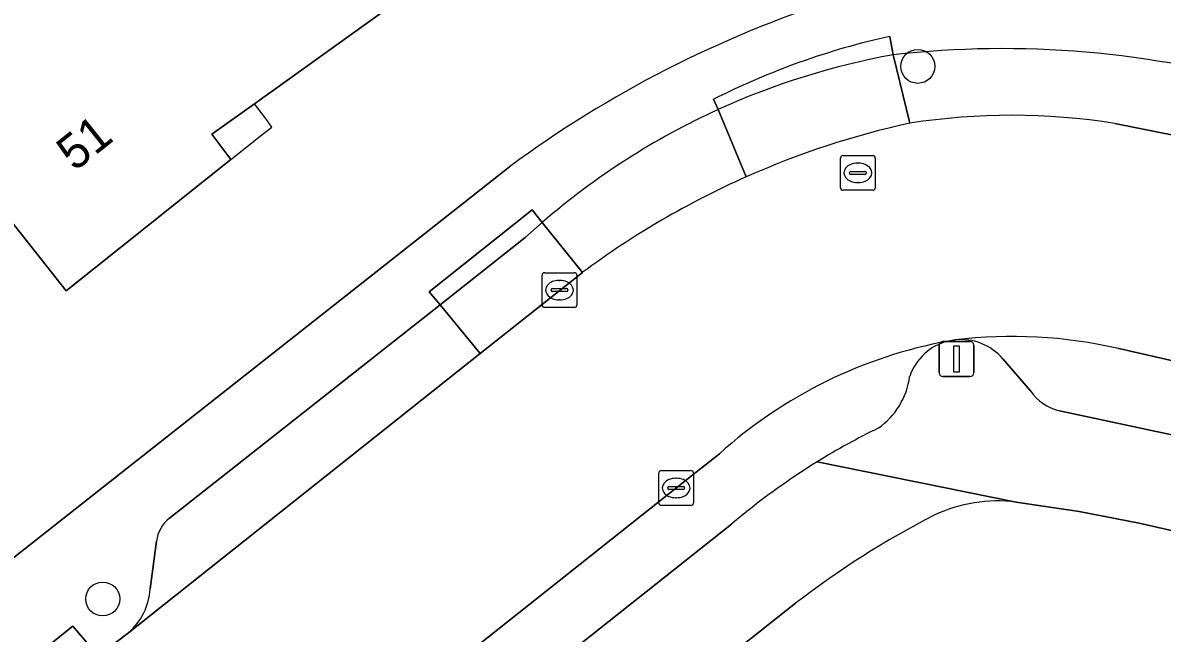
# Model space of a CAD drawing. Extents: x 159626 to 160723, y 388173 to 389416.
# Drawn here: x 160151.28 to 160184.07, y 388726.15 to 388743.72 of the extents above; entities that cross this region are included whole.
import ezdxf

# ---------------------------------------------------------------- set-up
doc = ezdxf.new("R2010")
doc.units = 0
for name, color, linetype in [('IMGEO_Boom', 7, 'Continuous'), ('IMGEO_Erf', 7, 'Continuous'), ('IMGEO_Kolk', 7, 'Continuous'), ('IMGEO_Lichtmast', 7, 'Continuous'), ('IMGEO_Pand', 7, 'Continuous'), ('IMGEO_Pand_nummerreeks', 7, 'Continuous'), ('IMGEO_Pand_overbouw', 7, 'Continuous'), ('IMGEO_Parkeervlak_open', 7, 'Continuous'), ('IMGEO_Rijbaan_lokaal_gesloten', 7, 'Continuous'), ('IMGEO_Rioolput', 7, 'Continuous'), ('IMGEO_Voetpad_open', 7, 'Continuous')]:
    doc.layers.add(name, color=color, linetype=linetype)

msp = doc.modelspace()

# ---------------------------------------------------------------- linework, layer by layer
at = {"layer": 'IMGEO_Boom'}
for centre in [(160177.036, 388742.463), (160153.582, 388727.138)]:
    msp.add_circle(centre, 0.489, dxfattribs=at)
at = {"layer": 'IMGEO_Erf'}
msp.add_lwpolyline([(160150.591, 388750), (160154.519, 388753.109), (160156.98, 388750), (160161.683, 388744.057), (160157.95, 388741.385), (160156.726, 388740.509), (160157.27, 388739.782), (160152.532, 388736.005), (160150.616, 388738.417), (160150.166, 388738.08), (160149.286, 388739.183), (160149.734, 388739.532), (160148.008, 388741.687), (160145.817, 388739.968), (160142.781, 388743.819)], close=True, dxfattribs=at)
for points in [[(160151.026, 388728.336), (160165.29, 388739.573)], [(160223.367, 388703.114), (160224.3, 388707.209), (160227.072, 388719.379), (160183.407, 388729.319), (160181.681, 388729.655), (160179.863, 388729.928)], [(160173.521, 388727.014), (160150.851, 388709.051), (160094.032, 388664.03)]]:
    msp.add_lwpolyline(points, dxfattribs=at)
for centre, radius, start, end in [((160184.6, 388713.456), 32.48, 107.7327, 126.4777), ((160179.343, 388725.64), 4.319, 83.0882, 115.1171), ((160189.291, 388706.623), 25.777, 117.195, 127.7176)]:
    msp.add_arc(centre, radius, start, end, dxfattribs=at)
at = {"layer": 'IMGEO_Kolk'}
for p, q in [((160166.225, 388735.599), (160166.225, 388736.451)), ((160166.3, 388736.525), (160167.152, 388736.525)), ((160167.226, 388736.451), (160167.226, 388735.599)), ((160166.484, 388736.019), (160166.484, 388736.031)), ((160166.527, 388736.068), (160166.925, 388736.068)), ((160166.713, 388736.305), (160166.738, 388736.305)), ((160166.968, 388736.031), (160166.968, 388736.019)), ((160166.922, 388735.982), (160166.524, 388735.982)), ((160166.736, 388735.745), (160166.711, 388735.745)), ((160167.152, 388735.525), (160166.3, 388735.525)), ((160169.582, 388729.905), (160169.582, 388730.757)), ((160169.657, 388730.831), (160170.509, 388730.831)), ((160170.583, 388730.757), (160170.583, 388729.905)), ((160170.07, 388730.611), (160170.095, 388730.611)), ((160169.841, 388730.325), (160169.841, 388730.337)), ((160170.279, 388730.288), (160169.881, 388730.288)), ((160169.884, 388730.374), (160170.282, 388730.374)), ((160170.325, 388730.337), (160170.325, 388730.325)), ((160170.509, 388729.831), (160169.657, 388729.831)), ((160170.093, 388730.051), (160170.068, 388730.051))]:
    msp.add_line(p, q, dxfattribs=at)
for points in [[(160166.225, 388735.599), (160166.225, 388736.451)], [(160166.3, 388736.525), (160167.152, 388736.525)], [(160167.226, 388736.451), (160167.226, 388735.599)], [(160167.152, 388735.525), (160166.3, 388735.525)], [(160169.582, 388729.905), (160169.582, 388730.757)], [(160169.657, 388730.831), (160170.509, 388730.831)], [(160170.583, 388730.757), (160170.583, 388729.905)], [(160170.509, 388729.831), (160169.657, 388729.831)]]:
    msp.add_lwpolyline(points, dxfattribs=at)
for centre, radius, start, end in [((160166.302, 388736.449), 0.0765, 91.552, 178.448), ((160166.302, 388736.449), 0.0765, 91.552, 178.448), ((160167.15, 388736.449), 0.0765, 1.552, 88.448), ((160167.15, 388736.449), 0.0765, 1.552, 88.448), ((160166.524, 388736.028), 0.0403, 85.8775, 175.7526), ((160166.521, 388736.018), 0.0366, 178.938, 274.7102), ((160166.925, 388736.025), 0.043, 264.8664, 352.4533), ((160166.929, 388736.03), 0.0386, 1.7309, 96.639), ((160166.302, 388735.601), 0.0765, 181.552, 268.448), ((160166.302, 388735.601), 0.0765, 181.552, 268.448), ((160167.15, 388735.601), 0.0765, 271.552, 358.448), ((160167.15, 388735.601), 0.0765, 271.552, 358.448), ((160169.659, 388730.755), 0.0765, 91.552, 178.448), ((160169.659, 388730.755), 0.0765, 91.552, 178.448), ((160170.507, 388730.755), 0.0765, 1.552, 88.448), ((160170.507, 388730.755), 0.0765, 1.552, 88.448), ((160169.881, 388730.334), 0.0403, 85.8775, 175.7526), ((160169.878, 388730.324), 0.0366, 178.938, 274.7102), ((160170.282, 388730.331), 0.043, 264.8664, 352.4533), ((160170.286, 388730.336), 0.0386, 1.7309, 96.639), ((160169.659, 388729.907), 0.0765, 181.552, 268.448), ((160169.659, 388729.907), 0.0765, 181.552, 268.448), ((160170.507, 388729.907), 0.0765, 271.552, 358.448), ((160170.507, 388729.907), 0.0765, 271.552, 358.448)]:
    msp.add_arc(centre, radius, start, end, dxfattribs=at)
for centre, major_axis, ratio, start_param, end_param in [((160166.712, 388736.025), (-0.387, 0.002), 0.722429, 4.712389, 7.853982), ((160166.737, 388736.025), (-0.39, 0.002), 0.717154, 1.570796, 4.712389), ((160170.069, 388730.331), (-0.387, 0.002), 0.722429, 4.712389, 7.853982), ((160170.094, 388730.331), (-0.39, 0.002), 0.717154, 1.570796, 4.712389)]:
    msp.add_ellipse(centre, major_axis=major_axis, ratio=ratio, start_param=start_param, end_param=end_param, dxfattribs=at)
at = {"layer": 'IMGEO_Lichtmast'}
for p, q in [((160177.655, 388733.643), (160177.655, 388734.443)), ((160177.655, 388734.443), (160177.655, 388733.643)), ((160177.755, 388734.543), (160178.545, 388734.543)), ((160178.545, 388734.543), (160177.755, 388734.543)), ((160178.645, 388734.443), (160178.645, 388733.643)), ((160178.645, 388733.643), (160178.645, 388734.443)), ((160178.545, 388733.543), (160177.755, 388733.543)), ((160177.755, 388733.543), (160178.545, 388733.543))]:
    msp.add_line(p, q, dxfattribs=at)
msp.add_lwpolyline([(160178.075, 388734.418), (160178.225, 388734.418), (160178.225, 388733.668), (160178.075, 388733.668), (160178.075, 388734.418)], dxfattribs=at)
for centre, start, end in [((160177.755, 388734.443), 90, 180), ((160177.755, 388734.443), 90, 180), ((160178.545, 388734.443), 0, 90), ((160178.545, 388734.443), 360, 90), ((160177.755, 388733.643), 180, 270), ((160177.755, 388733.643), 180, 270), ((160178.545, 388733.643), 270, 0), ((160178.545, 388733.643), 270, 0)]:
    msp.add_arc(centre, 0.1, start, end, dxfattribs=at)
at = {"layer": 'IMGEO_Pand'}
msp.add_lwpolyline([(160157.27, 388739.782), (160156.726, 388740.509), (160157.95, 388741.385), (160161.683, 388744.057), (160156.98, 388750), (160154.519, 388753.109), (160150.591, 388750), (160142.781, 388743.819), (160145.817, 388739.968), (160148.008, 388741.687), (160149.734, 388739.532), (160149.286, 388739.183), (160150.166, 388738.08), (160150.616, 388738.417), (160152.532, 388736.005)], close=True, dxfattribs=at)
at = {"layer": 'IMGEO_Pand_overbouw'}
msp.add_lwpolyline([(160157.27, 388739.782), (160158.208, 388740.528), (160158.446, 388740.716), (160158.268, 388740.968), (160157.95, 388741.385), (160156.726, 388740.509)], close=True, dxfattribs=at)
at = {"layer": 'IMGEO_Parkeervlak_open'}
for points in [[(160176.81, 388740.829), (160176.329, 388742.795)], [(160176.329, 388742.795), (160176.81, 388740.829)], [(160182.708, 388740.822), (160186.699, 388740.022), (160187.729, 388739.79), (160188.156, 388741.666), (160187.322, 388741.856)], [(160171.295, 388741.221), (160172.098, 388739.283)], [(160172.098, 388739.283), (160171.295, 388741.221)], [(160166.231, 388737.973), (160167.383, 388736.528)], [(160164.446, 388734.198), (160163.289, 388735.602), (160155.504, 388729.46)], [(160154.322, 388726.169), (160164.446, 388734.198)], [(160179.479, 388734.048), (160180.281, 388733.126)], [(160186.385, 388733.53), (160182.816, 388734.344)], [(160181.115, 388732.553), (160191.078, 388730.424), (160193.754, 388729.817), (160194.236, 388731.738), (160186.385, 388733.53)], [(160171.328, 388731.319), (160170.527, 388730.683), (160163.509, 388725.123), (160164.631, 388723.707), (160171.673, 388729.291)], [(160155.128, 388728.8), (160154.945, 388727.431)]]:
    msp.add_lwpolyline(points, dxfattribs=at)
msp.add_lwpolyline([(160167.383, 388736.528), (160166.231, 388737.973), (160165.742, 388737.537), (160163.289, 388735.602), (160164.446, 388734.198)], close=True, dxfattribs=at)
for centre, radius, start, end in [((160179.479, 388714.852), 28.12, 73.8041, 96.4315), ((160180.134, 388721.789), 21.348, 100.2671, 114.4591), ((160180.067, 388721.973), 21.152, 114.4999, 130.8515), ((160179.737, 388721.945), 19.109, 81.0545, 98.8095), ((160182.087, 388716.791), 24.611, 102.3822, 113.947), ((160182.134, 388716.694), 24.718, 113.956, 126.64), ((160179.751, 388721.039), 13.653, 77.0286, 96.9177), ((160180.354, 388721.285), 13.496, 100.3895, 131.9731), ((160178.285, 388733.039), 1.564, 103.489, 161.4297), ((160178.282, 388733.034), 1.569, 40.2698, 96.4013), ((160174.667, 388733.822), 2.154, 304.8505, 352.3843), ((160181.439, 388733.919), 1.404, 214.3806, 256.6373), ((160184.873, 388713.738), 20.398, 116.1031, 121.734), ((160185.108, 388713.394), 20.814, 121.7882, 130.2031), ((160156.132, 388728.665), 1.013, 128.301, 172.3589), ((160153.161, 388727.527), 1.786, 310.5258, 356.9267)]:
    msp.add_arc(centre, radius, start, end, dxfattribs=at)
at = {"layer": 'IMGEO_Rijbaan_lokaal_gesloten'}
for points in [[(160187.729, 388739.79), (160186.699, 388740.022), (160182.708, 388740.822)], [(160182.816, 388734.344), (160186.385, 388733.53), (160187.729, 388739.79)], [(160167.383, 388736.528), (160164.446, 388734.198), (160154.322, 388726.169), (160153.45, 388725.499), (160143.876, 388717.854), (160143.646, 388717.671), (160143.177, 388717.325), (160085.885, 388671.953), (160085.177, 388671.383), (160084.775, 388671.059), (160074.107, 388662.597), (160068.619, 388658.215), (160050.132, 388643.587), (160047.169, 388641.243), (160035.367, 388631.905), (160032.398, 388629.556), (160020.566, 388620.194), (160017.62, 388617.863), (160009.366, 388611.332), (160008.998, 388611.041), (160000, 388603.924), (159995.738, 388600.553), (159983.064, 388590.517)], [(160177.92, 388734.56), (160178.107, 388734.593)], [(160076.921, 388656.375), (160090.898, 388667.506), (160104.695, 388678.512), (160114.92, 388686.617), (160117.817, 388688.912), (160122.521, 388692.641), (160125.504, 388695.005), (160129.729, 388698.354), (160132.7, 388700.709), (160137.417, 388704.448), (160140.4, 388706.812), (160145.108, 388710.543), (160148.116, 388712.927), (160152.872, 388716.695), (160155.799, 388719.014), (160160.515, 388722.751), (160163.509, 388725.123), (160170.527, 388730.683), (160171.328, 388731.319)]]:
    msp.add_lwpolyline(points, dxfattribs=at)
for centre, radius, start, end in [((160179.737, 388721.945), 19.109, 81.0545, 98.8095), ((160182.087, 388716.791), 24.611, 102.3822, 113.947), ((160182.134, 388716.694), 24.718, 113.956, 126.64), ((160179.751, 388721.039), 13.653, 77.0286, 96.9177), ((160180.354, 388721.285), 13.496, 100.3895, 131.9731)]:
    msp.add_arc(centre, radius, start, end, dxfattribs=at)
at = {"layer": 'IMGEO_Rioolput'}
for p, q in [((160174.811, 388738.972), (160174.811, 388739.824)), ((160174.886, 388739.898), (160175.738, 388739.898)), ((160175.299, 388739.678), (160175.324, 388739.678)), ((160175.812, 388739.824), (160175.812, 388738.972)), ((160175.07, 388739.392), (160175.07, 388739.404)), ((160175.508, 388739.355), (160175.11, 388739.355)), ((160175.113, 388739.441), (160175.511, 388739.441)), ((160175.554, 388739.404), (160175.554, 388739.392)), ((160175.322, 388739.118), (160175.297, 388739.118)), ((160175.738, 388738.898), (160174.886, 388738.898))]:
    msp.add_line(p, q, dxfattribs=at)
for points in [[(160174.811, 388738.972), (160174.811, 388739.824)], [(160174.886, 388739.898), (160175.738, 388739.898)], [(160175.812, 388739.824), (160175.812, 388738.972)], [(160175.738, 388738.898), (160174.886, 388738.898)]]:
    msp.add_lwpolyline(points, dxfattribs=at)
for centre, radius, start, end in [((160174.888, 388739.822), 0.0765, 91.552, 178.448), ((160174.888, 388739.822), 0.0765, 91.552, 178.448), ((160175.736, 388739.822), 0.0765, 1.552, 88.448), ((160175.736, 388739.822), 0.0765, 1.552, 88.448), ((160175.11, 388739.401), 0.0403, 85.8775, 175.7526), ((160175.107, 388739.391), 0.0366, 178.938, 274.7102), ((160175.511, 388739.398), 0.043, 264.8664, 352.4533), ((160175.515, 388739.403), 0.0386, 1.7309, 96.639), ((160174.888, 388738.974), 0.0765, 181.552, 268.448), ((160174.888, 388738.974), 0.0765, 181.552, 268.448), ((160175.736, 388738.974), 0.0765, 271.552, 358.448), ((160175.736, 388738.974), 0.0765, 271.552, 358.448)]:
    msp.add_arc(centre, radius, start, end, dxfattribs=at)
for centre, major_axis, ratio, start_param, end_param in [((160175.298, 388739.398), (-0.387, 0.002), 0.722429, 4.712389, 7.853982), ((160175.323, 388739.398), (-0.39, 0.002), 0.717154, 1.570796, 4.712389)]:
    msp.add_ellipse(centre, major_axis=major_axis, ratio=ratio, start_param=start_param, end_param=end_param, dxfattribs=at)
at = {"layer": 'IMGEO_Voetpad_open'}
for points in [[(160176.329, 388742.795), (160176.227, 388743.325)], [(160176.227, 388743.325), (160176.329, 388742.795)], [(160171.161, 388741.517), (160171.295, 388741.221)], [(160171.295, 388741.221), (160171.161, 388741.517)], [(160165.29, 388739.573), (160151.026, 388728.336), (160148.356, 388726.193), (160144.483, 388723.108), (160141.674, 388720.846), (160141.623, 388720.804), (160141.571, 388720.763), (160143.176, 388718.737), (160152.726, 388726.356), (160153.45, 388725.499), (160154.322, 388726.169)], [(160155.504, 388729.46), (160163.289, 388735.602), (160162.975, 388735.98), (160165.94, 388738.338), (160166.231, 388737.973)], [(160178.107, 388734.593), (160177.92, 388734.56)], [(160180.281, 388733.126), (160179.479, 388734.048)], [(160225.081, 388722.687), (160224.97, 388722.2), (160221.258, 388723.045), (160221.37, 388723.533), (160216.013, 388724.754), (160215.9, 388724.267), (160212.213, 388725.108), (160212.324, 388725.595), (160206.742, 388726.865), (160206.631, 388726.377), (160202.914, 388727.223), (160203.025, 388727.71), (160197.447, 388728.98), (160197.336, 388728.492), (160193.643, 388729.33), (160193.754, 388729.817), (160191.078, 388730.424), (160181.115, 388732.553)], [(160174.144, 388731.086), (160179.863, 388729.928), (160181.681, 388729.655), (160183.407, 388729.319), (160227.072, 388719.379), (160229.749, 388718.77), (160237.27, 388717.058), (160321.781, 388697.748), (160325.989, 388696.807)], [(160179.863, 388729.928), (160174.144, 388731.086)], [(160171.673, 388729.291), (160164.631, 388723.707), (160164.937, 388723.291), (160161.984, 388720.933), (160161.651, 388721.344), (160156.924, 388717.596), (160157.256, 388717.174), (160154.299, 388714.833), (160153.975, 388715.258), (160149.234, 388711.499), (160149.555, 388711.088), (160149.36, 388710.933), (160146.591, 388708.735), (160146.258, 388709.139), (160141.535, 388705.394), (160141.859, 388704.99), (160138.878, 388702.645), (160138.561, 388703.035), (160133.838, 388699.29), (160134.15, 388698.902), (160131.172, 388696.547)], [(160154.945, 388727.431), (160155.128, 388728.8)], [(160089.067, 388660.444), (160094.032, 388664.03), (160150.851, 388709.051), (160173.521, 388727.014)]]:
    msp.add_lwpolyline(points, dxfattribs=at)
for points in [[(160163.289, 388735.602), (160165.742, 388737.537), (160166.231, 388737.973), (160165.94, 388738.338), (160162.975, 388735.98)], [(160143.876, 388717.854), (160153.45, 388725.499), (160152.726, 388726.356), (160143.176, 388718.737), (160142.947, 388718.554), (160143.646, 388717.671)]]:
    msp.add_lwpolyline(points, close=True, dxfattribs=at)
for centre, radius, start, end in [((160184.6, 388713.456), 32.48, 107.7327, 126.4777), ((160180.863, 388722.334), 21.496, 102.4536, 116.8282), ((160180.863, 388722.334), 21.496, 102.4536, 116.8282), ((160179.479, 388714.852), 28.12, 73.8041, 96.4315), ((160180.134, 388721.789), 21.348, 100.2671, 114.4591), ((160180.067, 388721.973), 21.152, 114.4999, 130.8515), ((160178.285, 388733.039), 1.564, 103.489, 161.4297), ((160178.282, 388733.034), 1.569, 40.2698, 96.4013), ((160174.667, 388733.822), 2.154, 304.8505, 352.3843), ((160181.439, 388733.919), 1.404, 214.3806, 256.6373), ((160184.873, 388713.738), 20.398, 116.1031, 121.734), ((160185.108, 388713.394), 20.814, 121.7882, 130.2031), ((160179.343, 388725.64), 4.319, 83.0882, 115.1171), ((160156.132, 388728.665), 1.013, 128.301, 172.3589), ((160189.291, 388706.623), 25.777, 117.195, 127.7176), ((160153.161, 388727.527), 1.786, 310.5258, 356.9267)]:
    msp.add_arc(centre, radius, start, end, dxfattribs=at)

# ---------------------------------------------------------------- texts
at = {"layer": 'IMGEO_Pand_nummerreeks'}
msp.add_text('51', height=1, rotation=38.5609, dxfattribs=at).set_placement((160152.773, 388739.419))

doc.saveas('drawing.dxf')
